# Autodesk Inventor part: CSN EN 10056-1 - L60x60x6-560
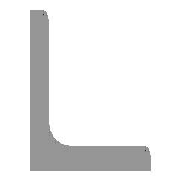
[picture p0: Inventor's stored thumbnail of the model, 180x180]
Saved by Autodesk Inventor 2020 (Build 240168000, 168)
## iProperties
Created: 2019-01
Part Number: CSN EN 10056-1 - L60x60x6-560
Material: Ocel, měkká
Description: Za tepla válcovaný konstrukcní ocelový profil - Rovnoramenné L2
Document SubType Name: Modeling
Standard: CSN EN 10056-1
Designer: doma
Standards Organization: CSN
Language: cs-CZ
Size Designation: L60x60x6-560
Categories: <MemberInstance><Categories><Category DisplayName="Konstrukční profily" InternalName="089c4875-fa83-4c05-b084-43b9cc11f5ed" Mnemonic="GRDR"><CategoryParameter D
Stock Number: L60x60x6
Density: 7.85 g/cm^3
Appearance: Pololeštěná
IsCustomPart: 1
G_L: 560,000 mm
Author: doma
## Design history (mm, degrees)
node "Počáteční rovina"
node "Koncová rovina"
sketch "Náčrt2"
  geometry: L1 (-10.873, -2.873)-(-10.873, 39.127); L2 (-16.873, 43.127)-(-14.873, 43.127); L3 (-16.873, -16.873)-(-16.873, 43.127); L4 (-16.873, -16.873)-(43.127, -16.873); L5 (43.127, -14.873)-(43.127, -16.873); L6 (-2.873, -10.873)-(39.127, -10.873); L7 (0, 60.87)-(0, -10.145) reference; L8 (-10.145, 0)-(60.87, 0) reference; A1 r 8 centre (-2.873, -2.873) between (-10.873, -2.873) and (-2.873, -10.873); A2 r 4 centre (-14.873, 39.127) between (-10.873, 39.127) and (-14.873, 43.127); A3 r 4 centre (39.127, -14.873) between (43.127, -14.873) and (39.127, -10.873); 3 further points
  constraints: 12 end point, 6 point on circle, 6 point on line, 6 tangent, 3 centre point, 3 horizontal, 3 vertical, 1 equal radius
  dimensions: "d4" = 60 distance of L3.start L4.end (= b); "d6" = 60 distance of L3.start L2.start (= b); "d8" = 6 distance of point (43.127, -10.873) L4.end (= ParT); "d10" = 6 distance of L2.start point (-10.873, 43.127) (= ParT); "d17" = 8 radius of A1 (= R); "d18" = 4 radius of A2 (= R1); "d19" = 16.87307 distance between parallel lines of L8 L4 (= ex); "d20" = 16.87307 distance between parallel lines of L3 L7 (= d19)
extrude "Těleso" new body sketch "Náčrt2" stored distance "d11" = 560 (= G_L); taper "d12" = 0 deg
node "Driven Length"
  sketch "Sketch3"
    geometry: L1 (0, 0)-(10, 0) reference
    constraints: 2 end point, 1 horizontal
  workplane "Work Plane10"
  sketch "Sketch4"
    geometry: L1 (-2, 0)-(12, 0) reference; L2 (-2, 560)-(12, 560) reference
    dimensions: "d24" = 560 distance between parallel lines of L1 L2 (derived)
sketch "Náčrt5"
  geometry: L1 (0, 0)-(133.258, 133.258); L2 (0, 0)-(188.455, 0); L3 (133.258, 133.258)-(133.258, -62.477); L4 (6, 0)-(6, 560) reference; L5 (133.258, -62.477)-(0, 0); L6 (60, 560)-(0, 560) reference; L7 (0, 560)-(170.228, 389.772); L8 (0, 560)-(240.739, 560); L9 (170.228, 389.772)-(179.753, 610.086); L10 (179.753, 610.086)-(0, 560); 3 further points
  constraints: 16 end point, 2 equal length, 2 horizontal, 1 parallel, 1 point on line
  dimensions: "d25" = 45 deg angle of L2 L1; "d26" = 45 deg angle of L7 L8
extrude "Vysunutí2" cut sketch "Náčrt5" extent not by distance; stored distance "d27" = 0; taper "d28" = 0 deg
sketch "Náčrt6"
  geometry: C1 r 3.5 at (30, -35) reference; C2 r 3.5 at (530, -35) reference; 3 further points
  constraints: 2 coincident
hole "Díra1" sketch "Náčrt6" at (530, -35), (30, -35) diameter "d29" = 4.917; stored, may be unused: countersink angle "d33" = 90 deg, drill point angle "d35" = 118 deg; dims "d30" = 12, "d31" = 4, "d32" = 2, "d34" = 17.1
chamfer "Zkosení1" distance "d36" = 3; stored, may be unused: second distance "d37" = 2, angle "d38" = 45 deg
chamfer "Zkosení2" distance "d39" = 3; stored, may be unused: second distance "d40" = 2, angle "d41" = 45 deg
body "Solid1"
node "Referenční1"
node "Referenční2"
other parameters: "b" = 60 [user parameter; used in 3 equation terms], "ParT" = 6 [user parameter; used in 3 equation terms], "R" = 8 [user parameter; used in 1 equation term], "R1" = 4 [user parameter; used in 1 equation term], "G_L" = 560 (= d24) [user parameter; used in 1 equation term], "d7" = 4 (derived), "d9" = 4 (derived), "ex" = 16.87307 (computed from b, ParT) [user parameter; used in 1 equation term], "G_OFFSET_START" = 0 [user parameter; used in 1 equation term], "G_OFFSET_END" = 0 [user parameter; used in 1 equation term], "d21" = 0 (computed from G_OFFSET_START), "d23" = 90 deg
